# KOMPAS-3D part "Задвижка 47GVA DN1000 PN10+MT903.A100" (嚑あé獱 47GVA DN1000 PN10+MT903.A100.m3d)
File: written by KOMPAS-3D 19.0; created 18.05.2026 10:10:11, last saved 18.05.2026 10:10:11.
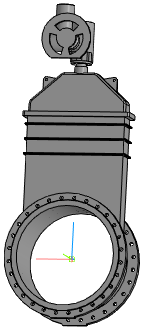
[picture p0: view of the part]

Document properties: Автор: Энергия; Полное имя файла: ..\Задвижка 47GVA DN40_DN1000+MT903.A\Задвижка 47GVA DN1000 PN10+MT903.A100.a3d

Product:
- Part/product: Задвижка 47GVA DN1000 PN10+MT903.A100
    Масса: 2919.37
  - Body: Электропривод МТ903.А100 без блока управления
      Масса: 346.451
  - Body: Задвижка 47GVA DN1000 PN10_F16 без исполнительного механизма
      Масса: 2572.92

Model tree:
1. Операция без истории:1
2. Операция без истории:2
